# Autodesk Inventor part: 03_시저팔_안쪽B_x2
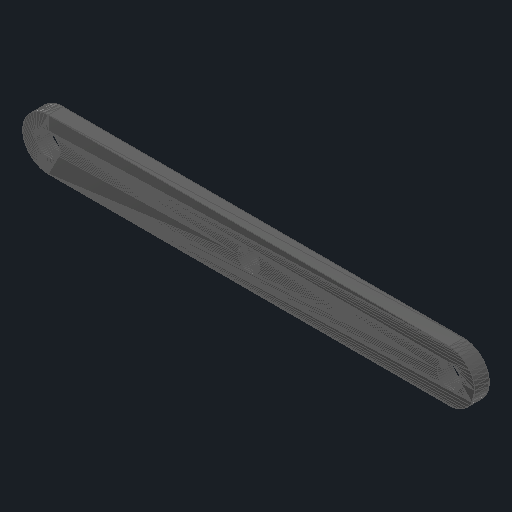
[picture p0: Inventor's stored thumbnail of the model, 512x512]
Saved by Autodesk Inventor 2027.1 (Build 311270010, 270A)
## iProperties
Created: 2026-11
Part Number: 03_시저팔_안쪽B_x2
Material: 일반
Document SubType Name: Modeling
Designer: djshs
Density: 1 g/cm^3
Appearance: 기본값
Author: djshs
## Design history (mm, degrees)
node "03_시저팔_안쪽B_x2"
  node "MeshFeature1"
